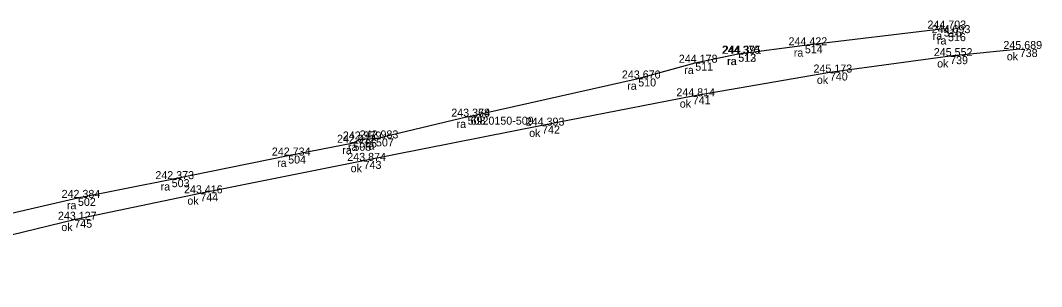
# Model space of a CAD drawing. Extents: x -759609 to -758899, y -1026011 to -1025762.
# Drawn here: x -759052.4 to -758899.3, y -1025801.7 to -1025761.8 of the extents above; entities that cross this region are included whole.
import ezdxf

# ---------------------------------------------------------------- set-up
doc = ezdxf.new("R2010")
doc.units = 0
for name, color, linetype in [('Vrstva 1', 7, 'Continuous'), ('Vrstva 28', 7, 'Continuous'), ('Vrstva 60', 7, 'Continuous'), ('Vrstva 61', 7, 'Continuous'), ('Vrstva 62', 7, 'Continuous')]:
    doc.layers.add(name, color=color, linetype=linetype)

msp = doc.modelspace()

# ---------------------------------------------------------------- linework, layer by layer
at = {"layer": 'Vrstva 1'}
msp.add_lwpolyline([(-758902.55, -1025766.11), (-758912.99, -1025767.18), (-758931.03, -1025769.64), (-758951.6, -1025773.2), (-758974.19, -1025777.6), (-759000.96, -1025782.89), (-759025.45, -1025787.76), (-759044.35, -1025791.72), (-759063.54, -1025796.36), (-759081.79, -1025801.74)], dxfattribs=at)
at = {"layer": 'Vrstva 28'}
msp.add_lwpolyline([(-759063.54, -1025793.03), (-759062.92, -1025792.84), (-759059.65, -1025792.08), (-759043.8, -1025788.44), (-759029.74, -1025785.63), (-759012.27, -1025782.09), (-759002.49, -1025780.17), (-759001.63, -1025779.68), (-758999.1, -1025779.52), (-758985.35, -1025776.25), (-758985.36, -1025776.26), (-758959.77, -1025770.53), (-758951.22, -1025768.17), (-758944.78, -1025766.82), (-758944.75, -1025766.82), (-758934.78, -1025765.55), (-758913.94, -1025763.04), (-758913.31, -1025763.73)], dxfattribs=at)
at = {"layer": 'Vrstva 60'}
for p, q in [((-758913.94, -1025763.04), (-758913.94, -1025763.04)), ((-758913.31, -1025763.73), (-758913.31, -1025763.73)), ((-758934.78, -1025765.55), (-758934.78, -1025765.55)), ((-758944.78, -1025766.82), (-758944.78, -1025766.82)), ((-758944.75, -1025766.82), (-758944.75, -1025766.82)), ((-758912.99, -1025767.18), (-758912.99, -1025767.18)), ((-758902.55, -1025766.11), (-758902.55, -1025766.11)), ((-758951.22, -1025768.17), (-758951.22, -1025768.17)), ((-758931.03, -1025769.64), (-758931.03, -1025769.64)), ((-758959.77, -1025770.53), (-758959.77, -1025770.53)), ((-758951.6, -1025773.2), (-758951.6, -1025773.2)), ((-758985.36, -1025776.26), (-758985.36, -1025776.26)), ((-758985.35, -1025776.25), (-758985.35, -1025776.25)), ((-758974.19, -1025777.6), (-758974.19, -1025777.6)), ((-758999.1, -1025779.52), (-758999.1, -1025779.52)), ((-759002.49, -1025780.17), (-759002.49, -1025780.17)), ((-759001.63, -1025779.68), (-759001.63, -1025779.68)), ((-759012.27, -1025782.09), (-759012.27, -1025782.09)), ((-759000.96, -1025782.89), (-759000.96, -1025782.89)), ((-759029.74, -1025785.63), (-759029.74, -1025785.63)), ((-759043.8, -1025788.44), (-759043.8, -1025788.44)), ((-759025.45, -1025787.76), (-759025.45, -1025787.76)), ((-759044.35, -1025791.72), (-759044.35, -1025791.72))]:
    msp.add_line(p, q, dxfattribs=at)

# ---------------------------------------------------------------- texts
for s, p in [('515', (-758913.94, -1025764.24)), ('516', (-758913.31, -1025764.93)), ('514', (-758934.78, -1025766.75)), ('512', (-758944.78, -1025768.02)), ('513', (-758944.75, -1025768.02)), ('739', (-758912.99, -1025768.38)), ('738', (-758902.55, -1025767.31)), ('511', (-758951.22, -1025769.36)), ('740', (-758931.03, -1025770.84)), ('510', (-758959.77, -1025771.72)), ('741', (-758951.6, -1025774.4)), ('508', (-758985.35, -1025777.45)), (' 6920150-509', (-758985.36, -1025777.46)), ('742', (-758974.19, -1025778.8)), ('507', (-758999.1, -1025780.72)), ('505', (-759002.49, -1025781.37)), ('506', (-759001.63, -1025780.88)), ('504', (-759012.27, -1025783.29)), ('743', (-759000.96, -1025784.09)), ('503', (-759029.74, -1025786.83)), ('502', (-759043.8, -1025789.64)), ('744', (-759025.45, -1025788.96)), ('745', (-759044.35, -1025792.92))]:
    msp.add_text(s, height=1.2, dxfattribs=at).set_placement(p)
at = {"layer": 'Vrstva 61'}
for s, p in [('244.703', (-758916.39, -1025763.04)), ('244.693', (-758915.76, -1025763.73)), ('244.422', (-758937.23, -1025765.55)), ('244.375', (-758947.24, -1025766.82)), ('244.391', (-758947.1, -1025766.82)), ('245.689', (-758905, -1025766.11)), ('244.178', (-758953.68, -1025768.17)), ('245.552', (-758915.44, -1025767.18)), ('245.173', (-758933.48, -1025769.64)), ('243.670', (-758962.22, -1025770.53)), ('244.814', (-758954.05, -1025773.2)), ('243.378', (-758987.81, -1025776.25)), ('243.364', (-758987.81, -1025776.26)), ('244.393', (-758976.64, -1025777.6)), ('242.912', (-759004.94, -1025780.17)), ('242.979', (-759004.08, -1025779.68)), ('242.983', (-759001.55, -1025779.52)), ('242.734', (-759014.72, -1025782.09)), ('243.874', (-759003.41, -1025782.89)), ('242.373', (-759032.19, -1025785.63)), ('242.384', (-759046.25, -1025788.44)), ('243.416', (-759027.9, -1025787.76)), ('243.127', (-759046.8, -1025791.72))]:
    msp.add_text(s, height=1.2, dxfattribs=at).set_placement(p)
at = {"layer": 'Vrstva 62'}
for s, p in [('ra', (-758915.6, -1025764.74)), ('ra', (-758914.97, -1025765.43)), ('ra', (-758936.44, -1025767.25)), ('ok', (-758904.49, -1025767.81)), ('ra', (-758952.88, -1025769.86)), ('ra', (-758946.45, -1025768.52)), ('ra', (-758946.41, -1025768.52)), ('ok', (-758914.94, -1025768.88)), ('ok', (-758932.98, -1025771.34)), ('ra', (-758961.43, -1025772.22)), ('ok', (-758953.54, -1025774.9)), ('ra', (-758987.02, -1025777.95)), ('ra', (-758987.02, -1025777.96)), ('ok', (-758976.13, -1025779.3)), ('ra', (-759004.15, -1025781.87)), ('ra', (-759003.29, -1025781.38)), ('ra', (-759000.76, -1025781.22)), ('ra', (-759013.93, -1025783.79)), ('ok', (-759002.9, -1025784.59)), ('ra', (-759031.4, -1025787.33)), ('ok', (-759027.39, -1025789.46)), ('ra', (-759045.46, -1025790.14)), ('ok', (-759046.29, -1025793.42))]:
    msp.add_text(s, height=1.2, dxfattribs=at).set_placement(p)

doc.saveas('drawing.dxf')
